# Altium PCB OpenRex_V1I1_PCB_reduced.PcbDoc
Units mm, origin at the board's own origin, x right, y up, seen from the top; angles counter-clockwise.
Board outline 70 x 95 mm, 10 copper layers (L1, L2, L3, L4 (PWR), L5 (PWR), L6 (PWR), L7 (PWR), L8, L9, L10), stack 1.632 mm thick; 1 components, 0 nets, 0 pads, 0 vias.
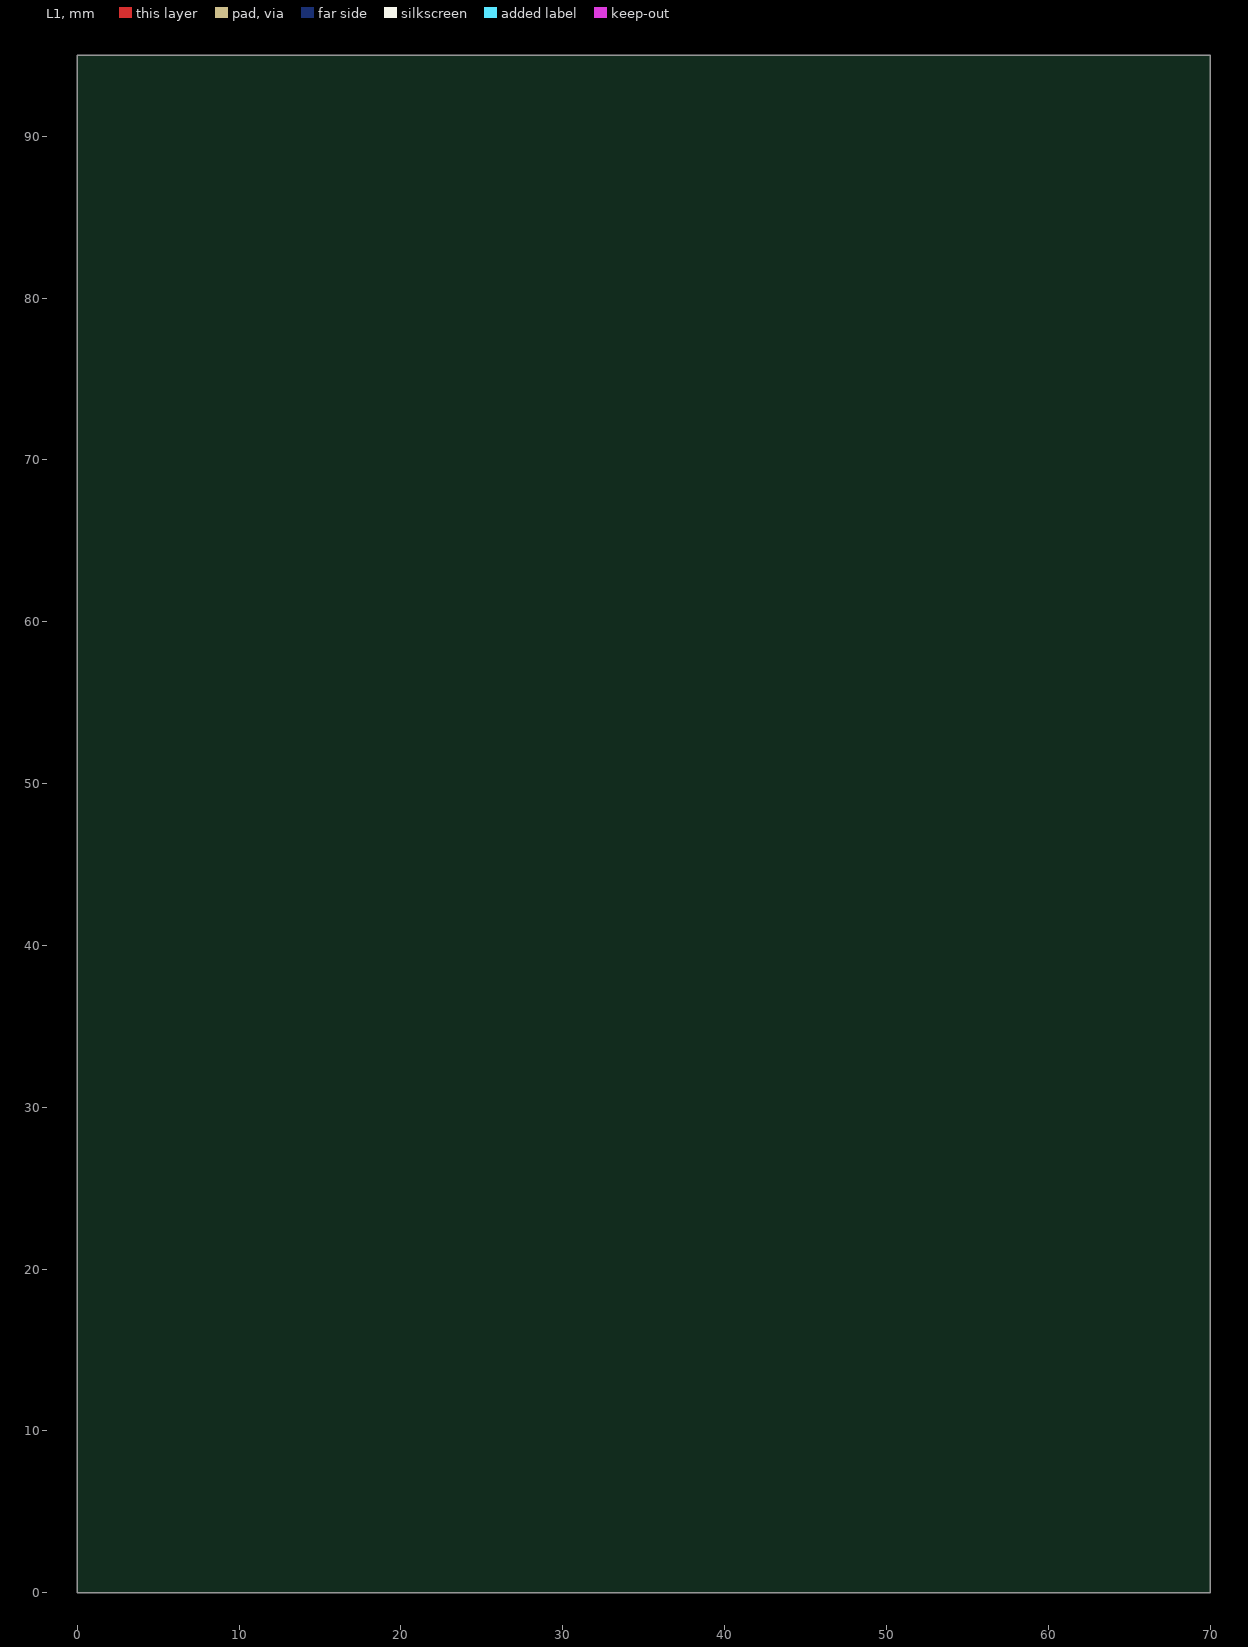
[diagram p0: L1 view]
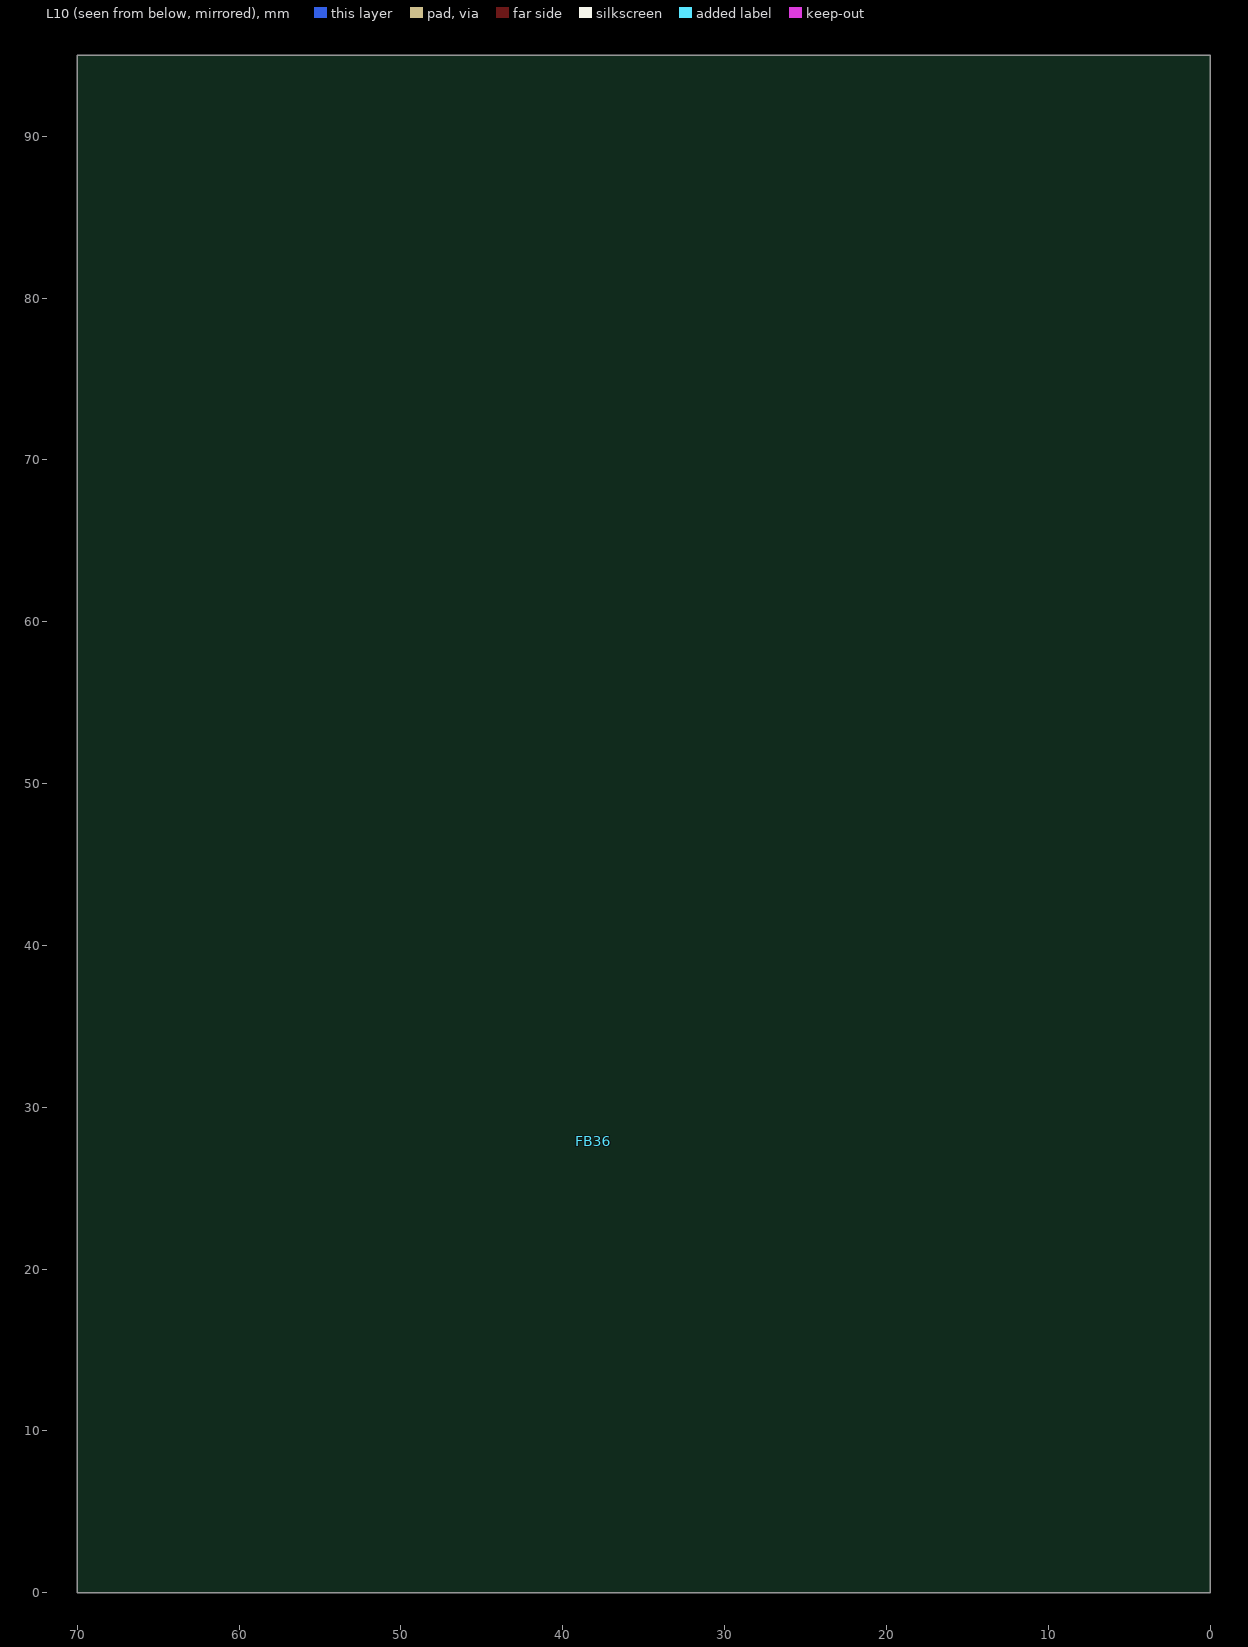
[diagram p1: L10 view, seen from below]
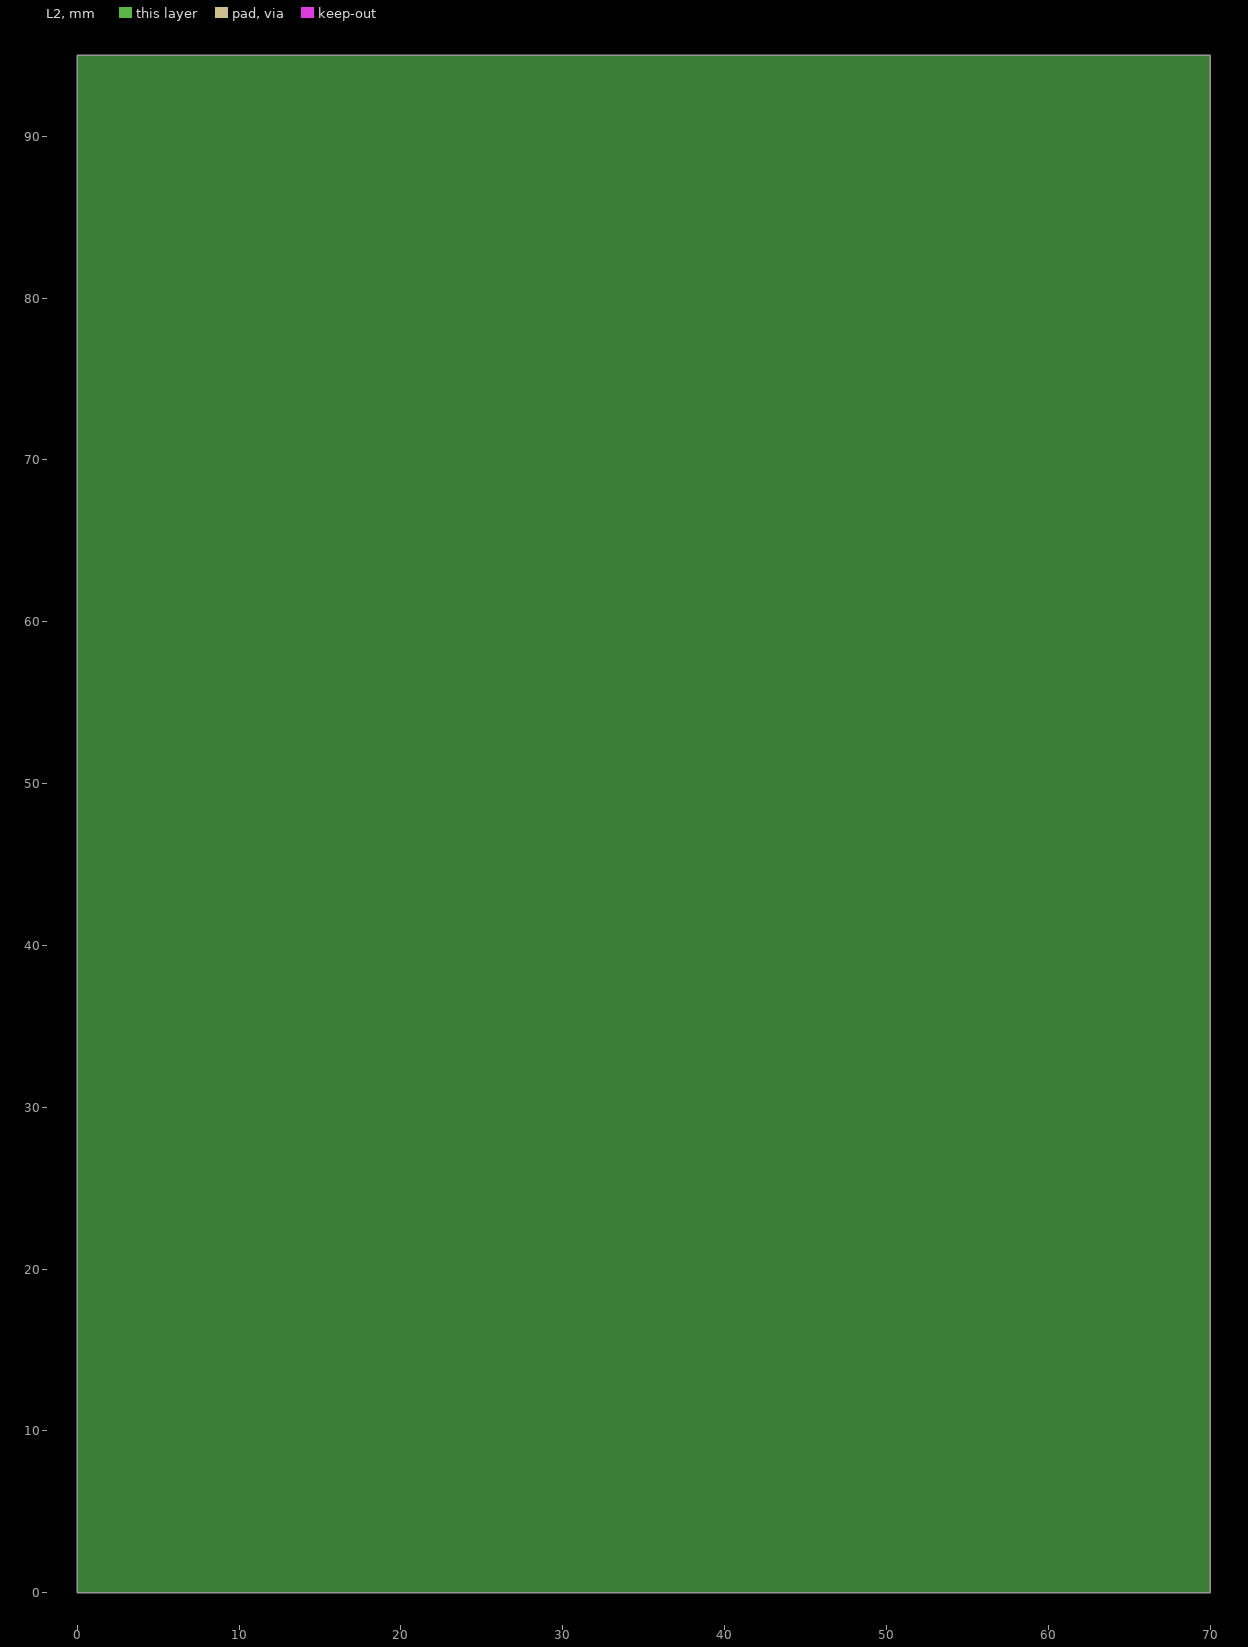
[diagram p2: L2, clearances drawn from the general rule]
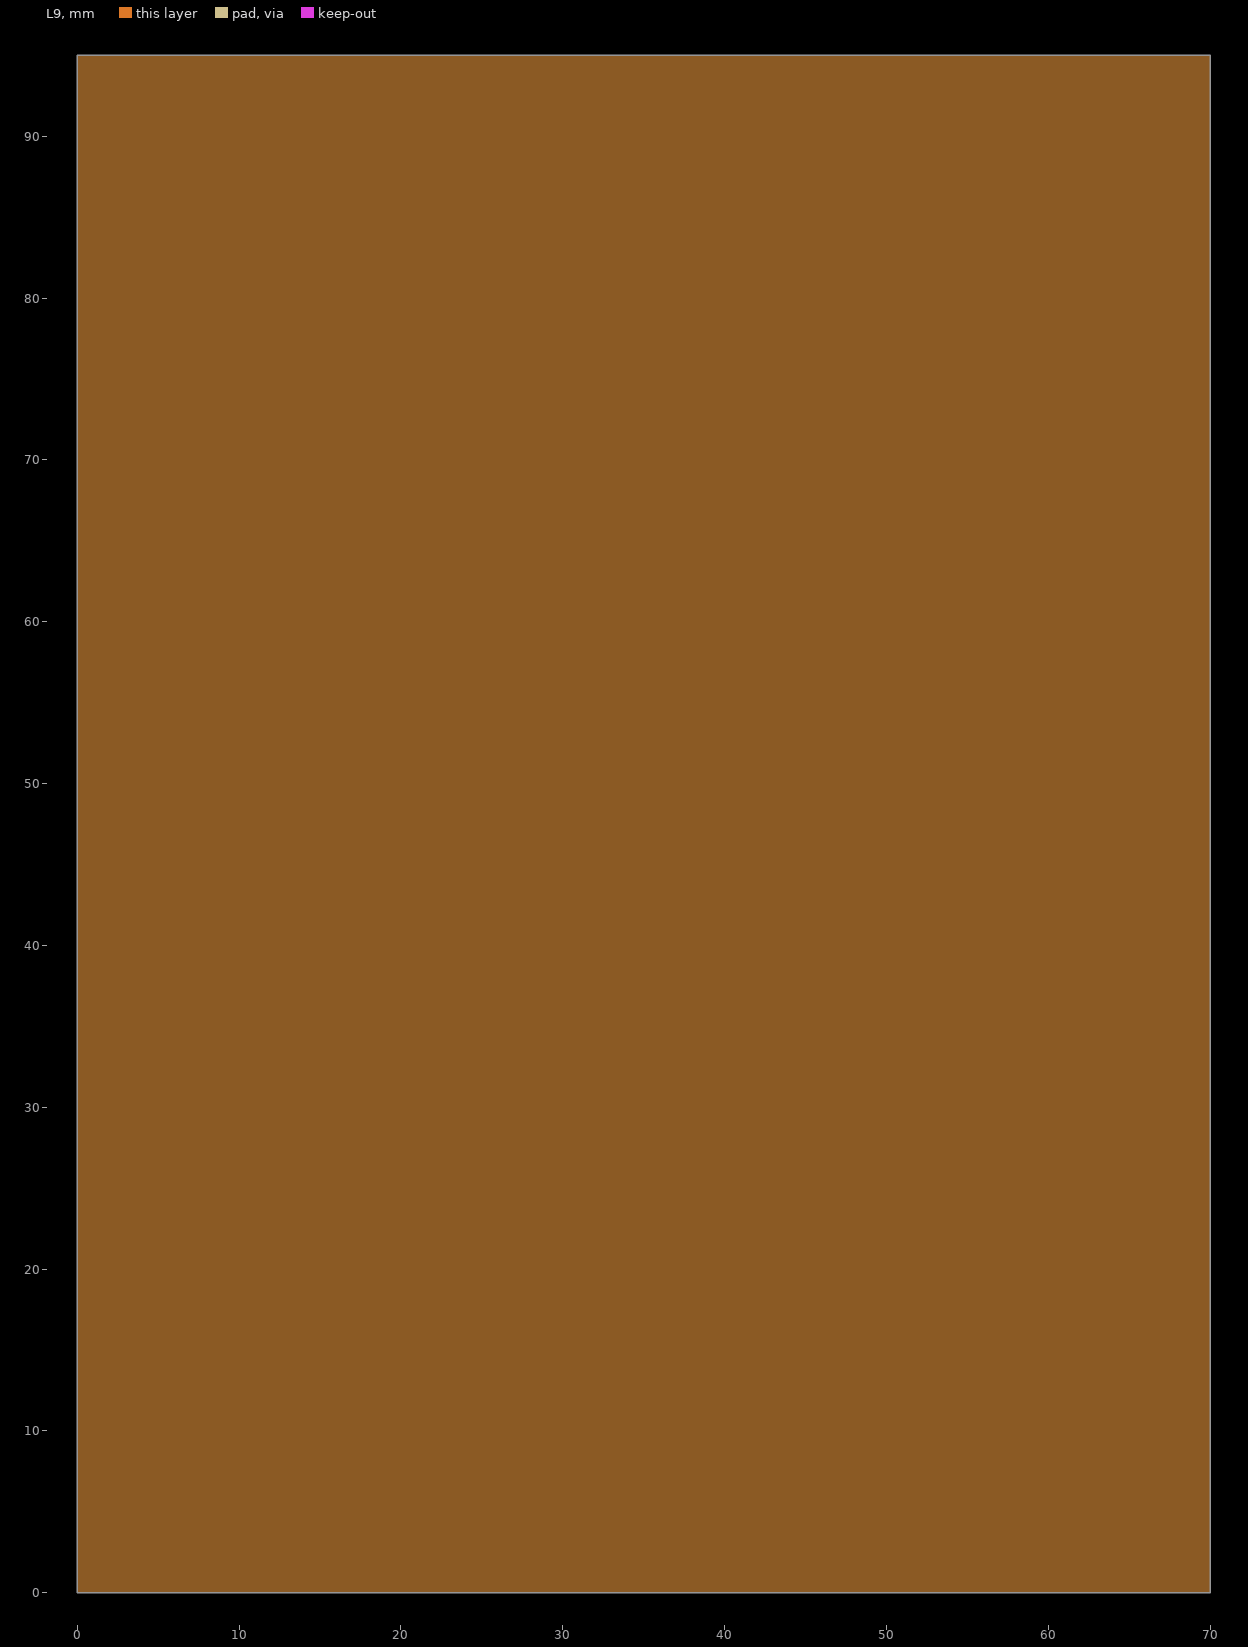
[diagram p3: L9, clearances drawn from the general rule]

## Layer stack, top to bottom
Top Solder: solder mask 0.02, Solder Resist, Dk 4.1
L1: signal copper 0.043
Dielectric1: core 0.074, VT47-1080, Dk 3.95
L2: plane copper 0.018, net GND
Dielectric2: prepreg 0.102, VT-47, Dk 4.12
L3: signal copper 0.018
Dielectric3: core 0.282, VT47-2113, Dk 4.06
L4 (PWR): signal copper 0.018
Dielectric4: prepreg 0.102, VT-47, Dk 4.12
L5 (PWR): signal copper 0.018
Dielectric 8: dielectric 0.282, VT47-2113, Dk 4.06
L6 (PWR): signal copper 0.018
Dielectric 9: dielectric 0.102, VT-47, Dk 4.12
L7 (PWR): signal copper 0.018
Dielectric5: core 0.282, VT47-2113, Dk 4.06
L8: signal copper 0.018
Dielectric6: prepreg 0.102, VT-47, Dk 4.12
L9: plane copper 0.018, net GND
Dielectric7: core 0.074, VT47-1080, Dk 3.95
L10: signal copper 0.043
Bottom Solder: solder mask 0.02, Solder Resist, Dk 4.1

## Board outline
0,0 70,0 70,95 0,95

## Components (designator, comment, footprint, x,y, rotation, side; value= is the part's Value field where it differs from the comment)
FB36 "" C0603 38.1,27.9 r0 bottom

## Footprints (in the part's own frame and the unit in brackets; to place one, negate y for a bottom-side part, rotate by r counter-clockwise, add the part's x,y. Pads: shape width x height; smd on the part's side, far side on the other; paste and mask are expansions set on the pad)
C0603 [mm]
  body extent -0.8,-0.42 0.8,0.44, height 0.95

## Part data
FB36: library part MPZ1608S601A, "FERRITE CHIP BEAD 600 OHM SMD 1A"

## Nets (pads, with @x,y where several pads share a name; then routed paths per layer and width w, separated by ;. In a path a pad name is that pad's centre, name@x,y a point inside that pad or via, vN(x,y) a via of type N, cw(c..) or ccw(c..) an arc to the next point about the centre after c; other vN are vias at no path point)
